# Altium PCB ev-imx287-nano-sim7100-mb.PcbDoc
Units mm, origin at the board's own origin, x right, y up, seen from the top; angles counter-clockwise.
Board outline 100 x 100 mm, 2 copper layers (Top Layer, Bottom Layer); 83 components, 89 nets, 510 pads, 495 vias.
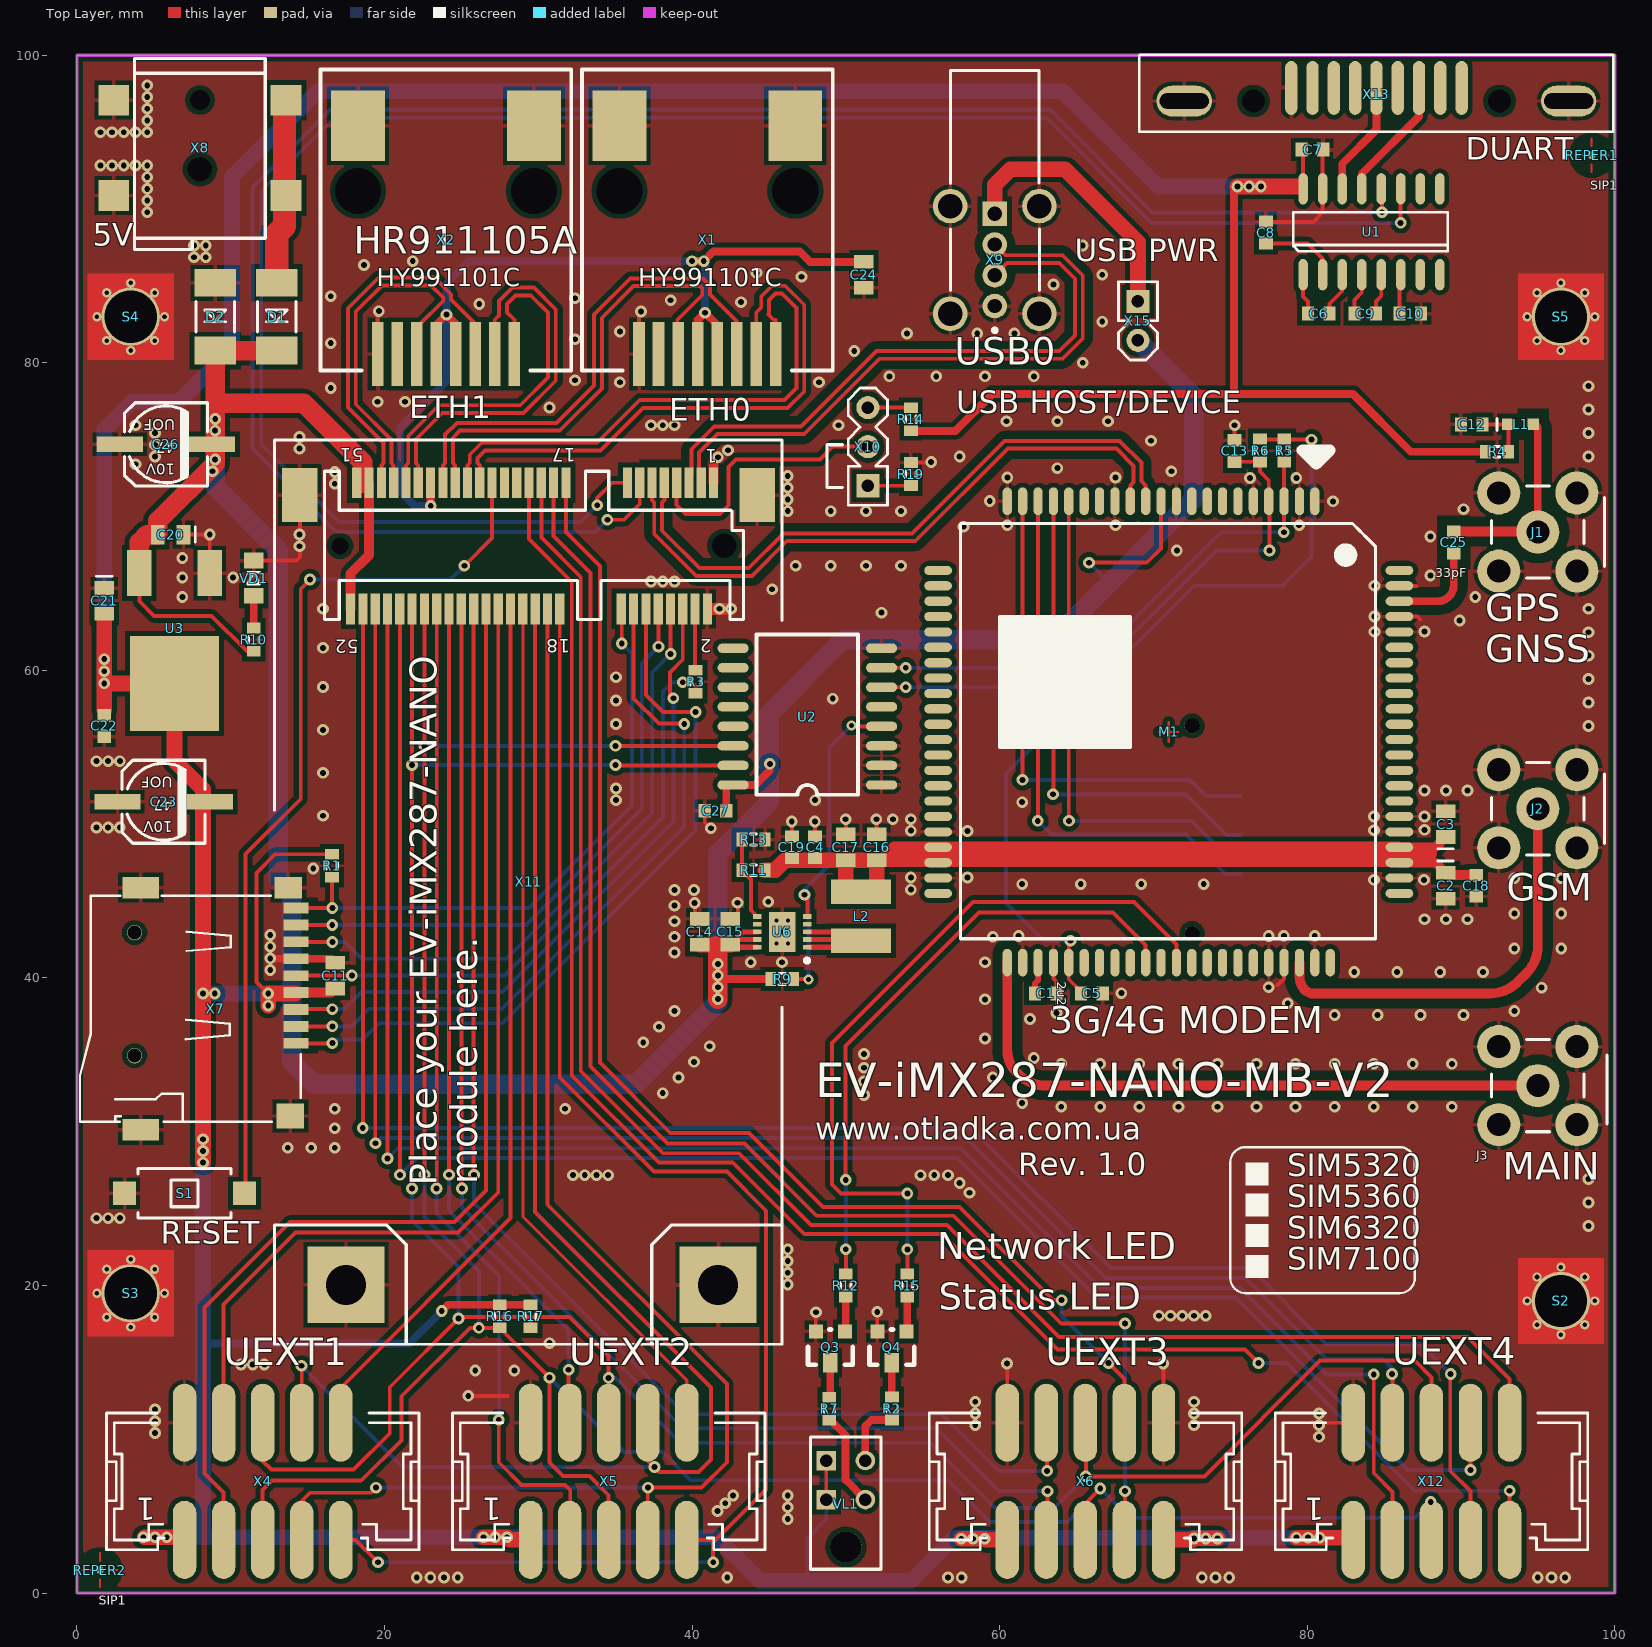
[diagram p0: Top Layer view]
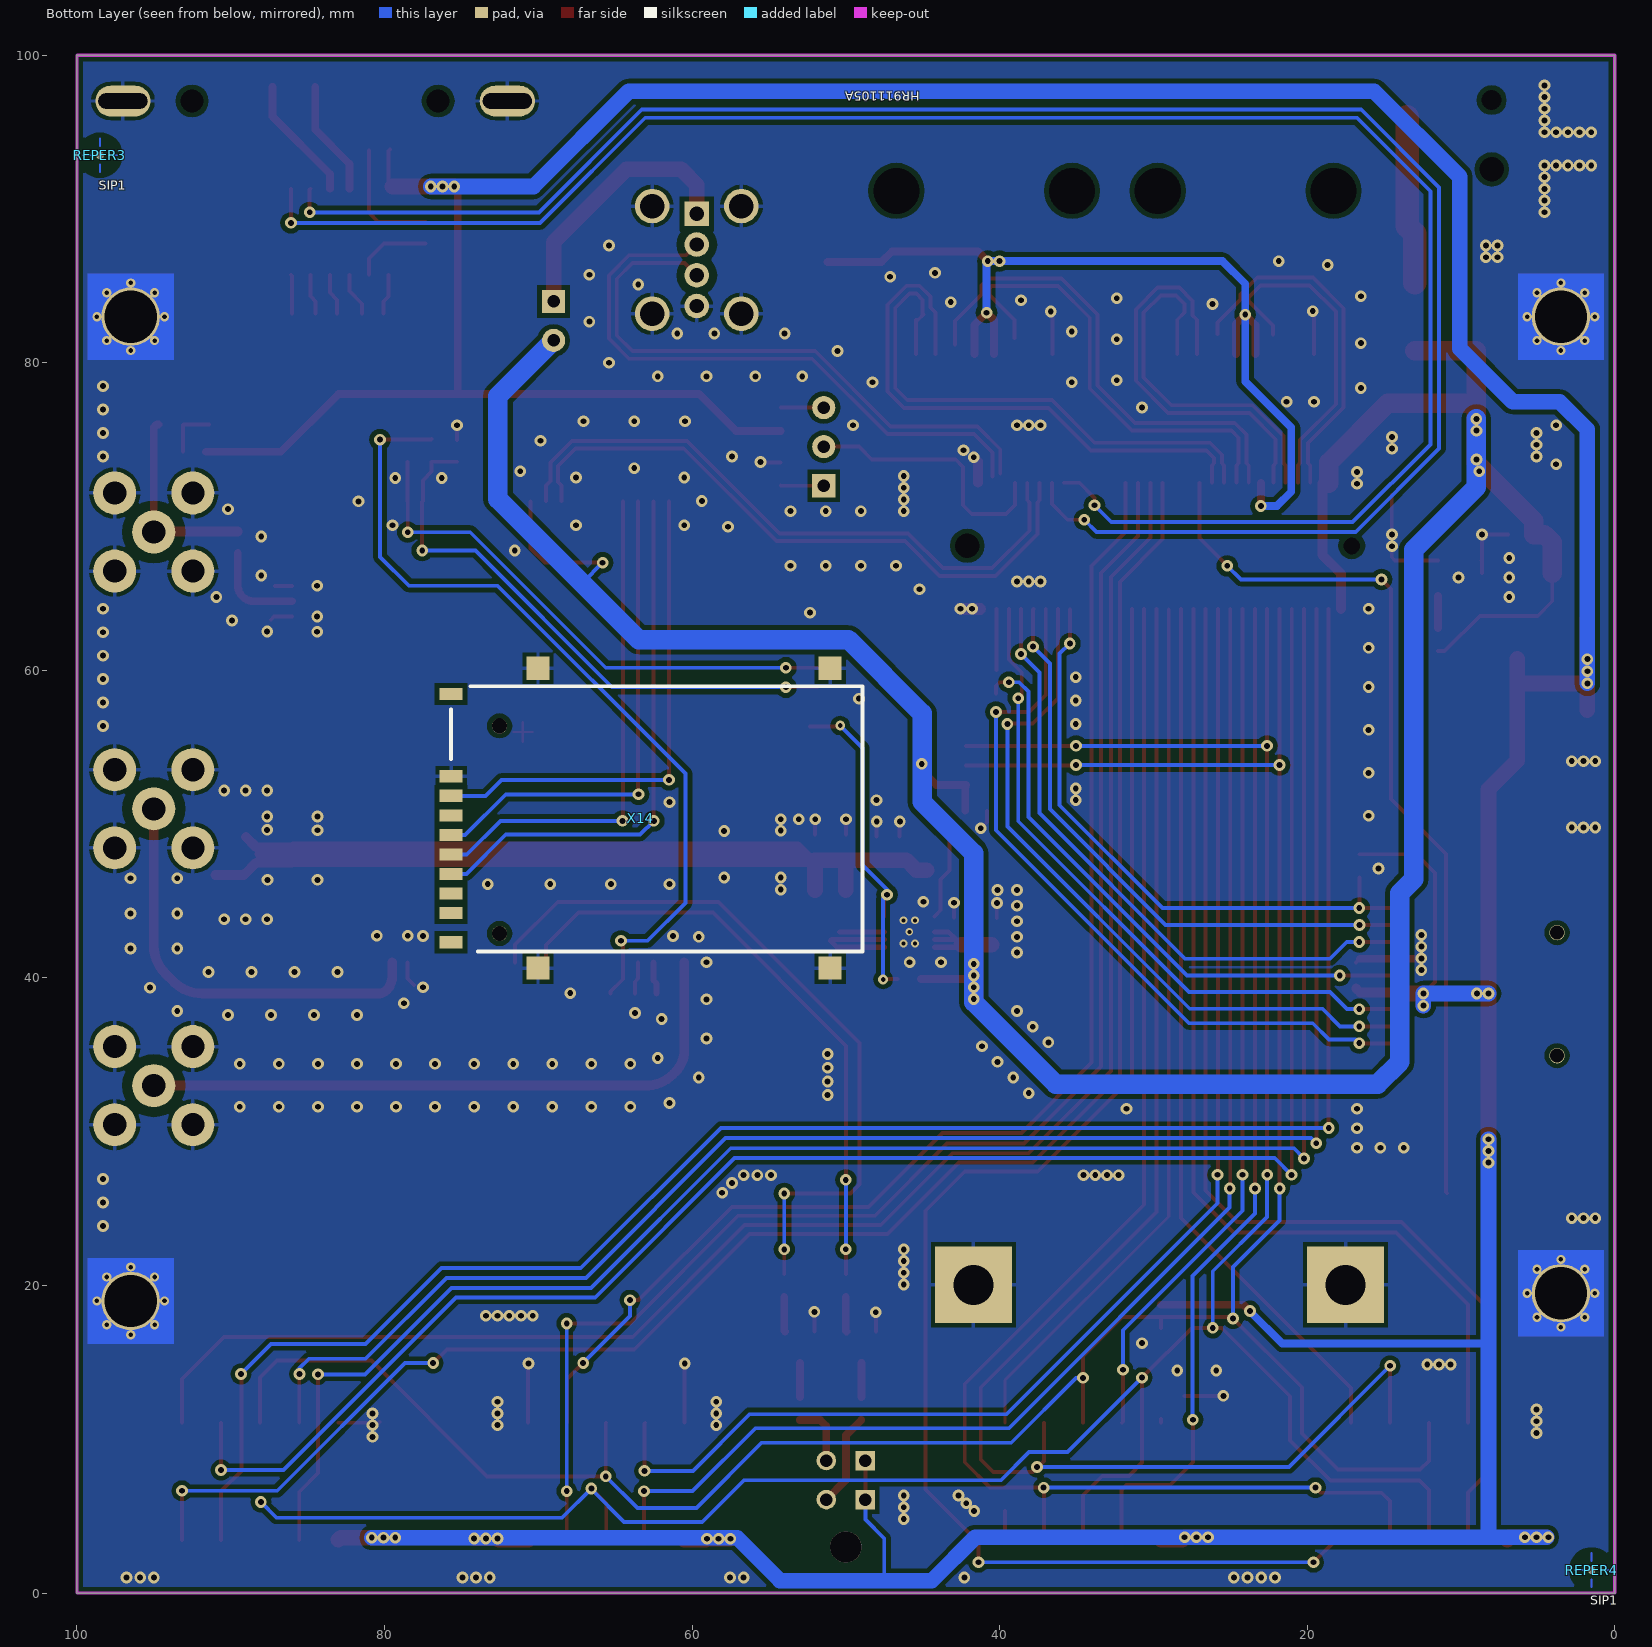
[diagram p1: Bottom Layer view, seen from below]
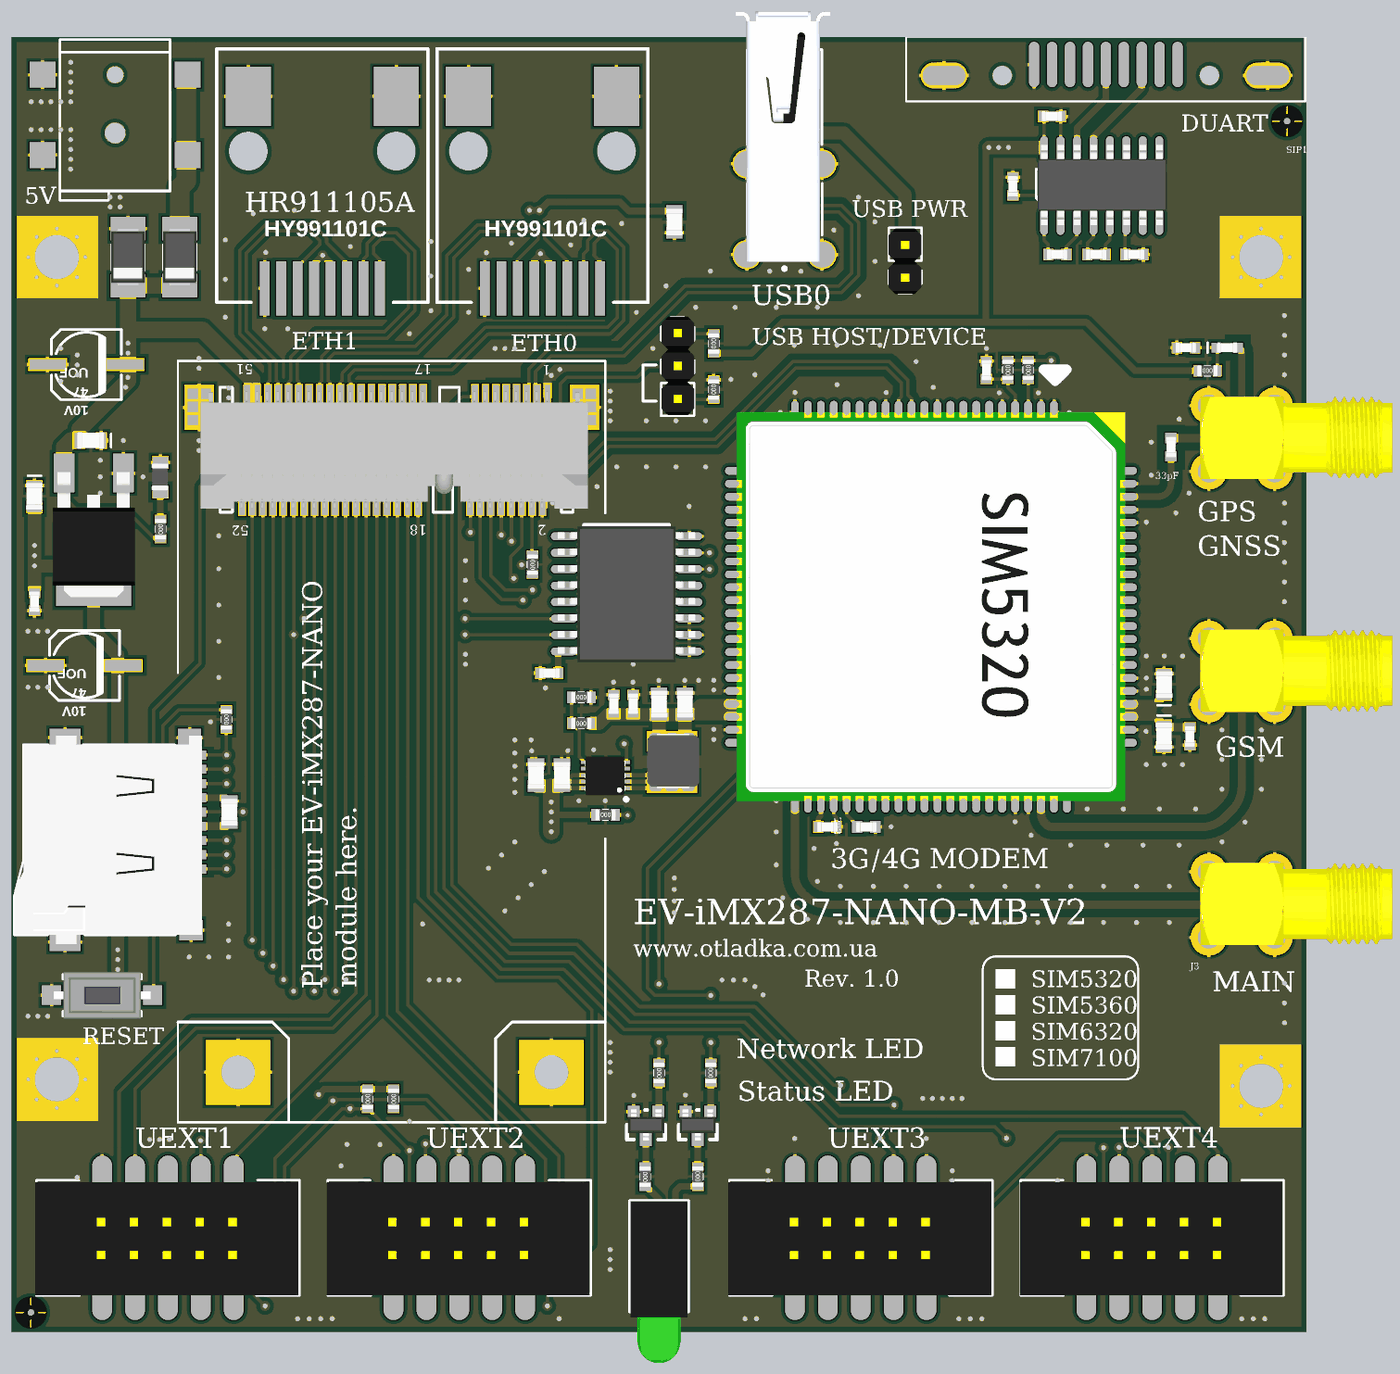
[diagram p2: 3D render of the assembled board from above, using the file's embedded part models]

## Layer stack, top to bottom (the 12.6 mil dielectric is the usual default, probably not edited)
Top Solder: solder mask 0.0102, Solder Resist, Dk 3.5
Top Layer: signal copper 0.0356
Dielectric1: dielectric 0.32, FR-4, Dk 4.8
Bottom Layer: signal copper 0.0356
Bottom Solder: solder mask 0.0102, Solder Resist, Dk 3.5

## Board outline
0,0 100,0 100,100 0,100

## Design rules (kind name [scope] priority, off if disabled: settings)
Clearance Clearance_3 [InNet('USB0_D_P') or InNet('USB0_D_N') or InNet('USB1_D_P') or InNet('USB1_D_N') vs InNet('GND')] p1: gap=0.508
Clearance Clearance_2 [InNet('GSM_ANT') or InNet('GPS_ANT') or InNet('MAIN_ANT') or InNet('NetC25_2') vs InNet('GND')] p2: gap=0.635
Clearance Clearance_1 [InPoly] p3: gap=0.305
Clearance [All] p4: gap=0.152
DiffPairsRouting [All] p1: maxlimit=0.254 minlimit=0.254 mostfreqgap=0.254 toplayer_minwidth=0.254 toplayer_maxwidth=0.254 toplayer_prefwidth=0.254 bottomlayer_minwidth=0.254 bottomlayer_maxwidth=0.254 bottomlayer_prefwidth=0.254 maxuncoupledlength=12.7
PolygonConnect PolygonConnect_2 [(InComponent('S3') or InComponent('S2'))] p1: connectstyle=Relief reliefconductorwidth=0.254 reliefentries=4 polygonreliefangle="45 Angle" airgapwidth=0.254
PolygonConnect PolygonConnect_1 [IsVia] p2: connectstyle=Direct reliefconductorwidth=0.254 reliefentries=4 polygonreliefangle="90 Angle" airgapwidth=0.254
PolygonConnect [IsPad] p3: connectstyle=Relief reliefconductorwidth=0.254 reliefentries=4 polygonreliefangle="90 Angle" airgapwidth=0.254
RoomDefinition ev287-sim7100-mb-rev1.0 [InComponentClass('ev287-sim7100-mb-rev1.0')] p1: confinementstyle=ConfineIn formatcopy=TRUE lockcomponents=FALSE outline -64.135,-65.786 -13.335,-65.786 -13.335,-40.386 -64.135,-40.386
RoutingVias [All] p1: holewidth=0.305 width=0.635 viastyle="Through Hole" minholewidth=0.305 minwidth=0.635 maxholewidth=0.305 maxwidth=0.635
SolderMaskExpansion [All] p1: expansion=0.102
Width [All] p1: maxlimit=2.54 minlimit=0.203 preferedwidth=0.254 minimp=50.000000 maximp=50.000000 favimp=50.000000
29 further rules are at their usual default settings.

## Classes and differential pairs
differential pair USB0_D: +USB0_D_P -USB0_D_N
differential pair USB1_D: +USB1_D_P -USB1_D_N
differential pair ETH0_RX: +ETH0_RX_P -ETH0_RX_N
differential pair ETH0_TX: +ETH0_TX_P -ETH0_TX_N
differential pair ETH1_RX: +ETH1_RX_P -ETH1_RX_N
differential pair ETH1_TX: +ETH1_TX_P -ETH1_TX_N

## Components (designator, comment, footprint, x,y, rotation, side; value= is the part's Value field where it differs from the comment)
C1 "0.1" IPC_C0603#1 63,39 r270 top
C2 "22u" IPC_C0805#1 89,46 r270 top
C3 "22u" IPC_C0805#1 89,50 r90 top
C4 "0.1" IPC_C0603#1 48,48.5 r0 top
C5 "2u2" IPC_C0603#2 66,39 r270 top
C6 "0.1" IPC_C0603#1 80.757,83.2 r90 top
C7 "0.1" IPC_C0603#1 80.351,93.868 r90 top
C8 "0.1" IPC_C0603#1 77.318,88.468 r0 top
C9 "0.1" IPC_C0603#1 83.78,83.2 r90 top
C10 "0.1" IPC_C0603#1 86.701,83.2 r90 top
C11 "22uF" IPC_C0805#2 16.815,40.157 r0 top
C12 "1u" IPC_C0603#1 90.7,76 r90 top
C13 "0.1" IPC_C0603#1 75.286,74.27 r0 top
C14 "22u" ipc_c0805 40.5,43 r0 top
C15 "22u" ipc_c0805 42.5,43 r0 top
C16 "22u" IPC_C0805#2 52,48.5 r0 top
C17 "22u" IPC_C0805#2 50,48.5 r0 top
C18 "0.1" IPC_C0603#1 91,46 r180 top
C19 "0.1" IPC_C0603#1 46.5,48.5 r0 top
C20 "22u" IPC_C0805#1 6.096,68.834 r180 top
C21 "22u" IPC_C0805#1 1.778,64.516 r270 top
C22 "0.1" IPC_C0603#1 1.778,56.388 r0 top
C23 "100u/35V" ALU_SMD_5.3 5.639,51.46 r270 top
C24 "22u" IPC_C0805#2 51.181,85.725 r0 top
C25 "33pF" IPC_C0603#2 89.535,68.326 r0 top
C26 "100u/35V" ALU_SMD_5.3 5.791,74.701 r270 top
C27 "0.1" IPC_C0603#1 41.529,50.876 r270 top
D1 "B340A" SMA 13,83 r90 top
D2 "TVS 6V" SMA 9,83 r90 top
J1 "GPS" SMA_RF 95,69 r90 top
J2 "GSM" SMA_RF 95,51 r90 top
J3 "MAIN" SMA_RF 95,33 r90 top
L1 "FB" L0603 93.875,76 r180 top
L2 "2.2uH/2A" VLCF4020 51,44 r180 top
M1 "SIM7100C" SIM7100C 71,56 r270 top locked
Q3 "BC817" SOT23 49,16 r180 top
Q4 "BC817" SOT23 53,16 r180 top
R1 "10K" IPC_R0603#1 16.586,47.295 r0 top
R2 "510" IPC_R0603#1 53,12 r180 top
R3 "22R" IPC_R0603#1 40.234,59.258 r0 top
R4 "10R" IPC_R0603#1 92.351,74.222 r90 top
R5 "10K" IPC_R0603#1 78.511,74.295 r0 top
R6 "10K" IPC_R0603#1 76.937,74.295 r0 top
R7 "1K" IPC_R0603#2 48.92,11.989 r0 top
R9 "10K" IPC_R0603#2 45.872,39.929 r90 top
R10 "560R" IPC_R0603#1 11.5,62 r0 top
R11 "12K1" IPC_R0603#1 44,47 r270 top
R12 "1K" IPC_R0603#1 50,20 r0 top
R13 "2K" IPC_R0603#2 44,49 r90 top
R14 "1K" IPC_R0603#1 54.229,76.327 r180 top
R15 "1K" IPC_R0603#1 54,20 r180 top
R16 "2K2" IPC_R0603#1 27.5,18 r0 top
R17 "2K2" IPC_R0603#1 29.5,18 r0 top
R19 "1K" IPC_R0603#1 54.229,72.771 r180 top
REPER1 "SIP1" reper2 98.5,93.5 r0 top
REPER2 "SIP1" reper2 1.5,1.5 r0 top
REPER3 "SIP1" reper2 98.5,93.5 r180 bottom
REPER4 "SIP1" reper2 1.5,1.5 r180 bottom
S1 "RESET" TS-101 7,26 r180 top
S2 "SIP1" MOUNTING_HOLE_3MM 96.5,19 r0 top
S3 "SIP1" MOUNTING_HOLE_3MM 3.5,19.5 r0 top
S4 "SIP1" MOUNTING_HOLE_3MM 3.5,83 r0 top
S5 "SIP1" MOUNTING_HOLE_3MM 96.5,83 r0 top
U1 "MAX3232E" SO-16 84.184,88.524 r90 top
U2 "PCF8574" SOL-16 47.498,56.998 r180 top
U3 "NCP1117-33" DPAK 6.35,62.738 r90 top
U6 "NCP1593B" DFN10 47.5,42 r90 top
VD1 "POWER" l0805 11.5,66 r270 top
VL1 "Modem LEDs" LED3_2F 50,3 r0 top
X1 "HR911105A" ETH3A_SMD 41,87.5 r0 top
X2 "HR911105A" ETH3A_SMD 24,87.5 r0 top
X4 "UEXT1" BH10_SMT 7,6 r180 top
X5 "UEXT2" BH10_SMT 29.5,6 r180 top
X6 "UEXT3" BH10_SMT 60.5,6 r180 top (schematic designator X14)
X7 "SDCARD" mSD_TF_push 9,38 r270 top
X8 "POWER" DJK-03-SMD 8.001,93.98 r180 top
X9 "USB0" USB-AC-EDGE 59.69,83.693 r0 top
X10 "USBID" SIP3 51.435,72.009 r90 top
X11 "" PCIEXPRESS_mini 45,76 r180 top
X12 "UEXT4" BH10_SMT 83,6 r180 top
X13 "DUART" DR9P 84.506,100.025 r180 top
X14 "SIM_ASTRON" SIM_ASTRON 75.667,53.111 r90 bottom locked (schematic designator X6)
X15 "USBPWR" SIP2 69,84 r0 top

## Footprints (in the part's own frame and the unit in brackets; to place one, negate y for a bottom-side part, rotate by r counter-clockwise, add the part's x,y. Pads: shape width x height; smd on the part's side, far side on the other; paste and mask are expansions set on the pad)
ALU_SMD_5.3 [mm]
  rect 1x3 smd paste-0.1: 1(0,3) 2(0,-3)
  silkscreen extent -2.7,-2.7 2.7,2.7
BH10_SMT [mil]
  oval 60x200 smd: 1(0,100) 2(0,-200) 3(-100,100) 4(-100,-200) 5(-200,100) 6(-200,-200) 7(-300,100) 8(-300,-200) 9(-400,100) 10(-400,-200)
  silkscreen extent -600,-225 200,125, body extent -597,-219 203,125, height 344
DFN10 [mm]
  rect 0.3x0.56 smd paste-0.025: 1(0,0) 2(0.5,0) 3(1,0) 4(1.5,0) 5(2,0) 6(2,3.258) 7(1.5,3.258) 8(1,3.258) 9(0.5,3.258) 10(0,3.258)
  rect 2.6x1.7 smd paste-1.27: 11(1,1.629)
  rrect50% 0.6x0.6 on Top Paste: 15(0.25,2.054) 15(1,1.629) 16(0.25,1.254) 17(1.65,1.254) 18(1.65,2.054)
  silkscreen extent -1,-0.11 -0.73,0.17, body extent -0.55,0.1 2.45,3.2, height 1
DJK-03-SMD [mm]
  round 1.5 hole 1.6: 0(0,1.4)
  round 1.2 hole 1.3: 0(0,-3.1)
  rect 2x2 smd: 1(5.6,-3.1) 2(-5.6,3.1) 2(-5.6,-3.1) 3(5.6,3.1)
  silkscreen extent -4.25,-5.82 4.25,6.6
DPAK [mm]
  rect 3x1.6 smd: 1(3.59,-2.29) 2(-2,0) 3(3.59,2.29)
  rect 6.2x5.8 smd: 4(-3.59,0)
  body extent -5.98,-3.17 3.66,3.18, height 2.18
DR9P [mm]
  round 1.3 hole 1.5: 0(-8,3) 0(8,3)
  oval 0.8x3.5 smd: 1(-5.54,2.15) 2(-2.77,2.15) 3(0,2.15) 4(2.77,2.15) 5(5.54,2.15) 6(-4.155,2.15) 7(-1.385,2.15) 8(1.385,2.15) 9(4.155,2.15)
  oval 3.6x2 hole 1 slot 3.2 at 0 deg: 10(-12.5,3) 11(12.5,3)
  silkscreen extent -15.4,0 15.43,5
ETH3A_SMD [mm]
  round 2.8 hole 3 unplated: 0(-5.715,3.685) 0(5.715,3.685)
  rect 0.76x4.18 smd: 1(4.445,-6.925) 2(3.175,-6.925) 3(1.905,-6.925) 4(0.635,-6.925) 5(-0.635,-6.925) 6(-1.905,-6.925) 7(-3.175,-6.925) 8(-4.445,-6.925)
  rect 3.5x4.58 smd: 15(-5.715,7.925) 16(5.715,7.925)
  silkscreen extent -8.15,-8 8.15,11.59
IPC_C0603#1 [mm]
  rect 0.9x0.8 smd paste-0.051: 1(0,-0.7) 2(0,0.7)
  body extent -0.39,-0.79 0.41,0.81, height 0.88
IPC_C0603#2 [mm]
  rect 0.9x0.8 smd: 1(0,-0.7) 2(0,0.7)
  body extent -0.39,-0.79 0.41,0.81, height 0.88
IPC_C0805#1 [mil]
  rect 35x50 smd paste-3: 1(-33,0) 2(33,0)
  silkscreen extent -63,-20 -63,20, body extent -42,-26 41,25, height 20
IPC_C0805#2 [mil]
  rect 50x35 smd: 1(0,-33) 2(0,33)
  body extent -25,-42 26,41, height 20
ipc_c0805 [mil]
  rect 50x35 smd: 1(0,-33) 2(0,33)
  body extent -25,-42 26,41, height 20
IPC_R0603#1 [mm]
  rect 0.9x0.7 smd paste-0.051: 1(0,-0.75) 2(0,0.75)
  silkscreen extent -0.35,-0.2 0.35,0.2, body extent -0.44,-0.8 0.46,0.8, height 0.5
IPC_R0603#2 [mm]
  rect 0.9x0.7 smd: 1(0,-0.75) 2(0,0.75)
  silkscreen extent -0.35,-0.2 0.35,0.2, body extent -0.44,-0.8 0.46,0.8, height 0.5
L0603 [mil]
  rect 30x30 smd: 1(32.5,0) 2(-32.5,0)
  silkscreen extent 60,-15 60,15, body extent -31,-16 32,15, height 35
l0805 [mil]
  rect 40x50 smd paste-2: 1(45,0) 2(-45,0)
  silkscreen extent -15,-15 15,15, body extent -42,-27 40,25, height 20
LED3_2F [mil]
  rect 50x50 hole 32: 1(-50,221.26) 3(-50,121.26)
  round 50 hole 32: 2(50,221.26) 4(50,121.26)
  round 80 hole 80: 5(0,0)
  silkscreen extent -90,-57 90,281, body extent -87,-212 87,280, height 378
MOUNTING_HOLE_3MM [mm]
  round 3.8 hole 3.4 mask+0.2: 1(0,0)
  Top Layer region: -2.8,-2.8 2.8,-2.8 2.8,2.8 -2.8,2.8
  Bottom Layer region: -2.8,-2.8 2.8,-2.8 2.8,2.8 -2.8,2.8
mSD_TF_push [mm]
  rect 0.7x1.6 smd: 1(2.25,5.25) 2(1.15,5.25) 3(0.05,5.25) 4(-1.05,5.25) 5(-2.15,5.25) 6(-3.25,5.25) 7(-4.35,5.25) 8(-5.45,5.25) 11(-6.55,5.25)
  rect 1.4x1.8 smd: 12(-7.875,4.75)
  rect 1.4x2.4 smd: 12(-7.875,-4.85) 12(7.875,-4.85)
  rect 1.6x1.8 smd: 12(6.975,4.875)
  round 1 hole 0.9: 13(-4.95,-5.25) 14(3.05,-5.25)
  silkscreen extent -7.35,-8.8 7.35,5.55, body extent -8.05,-8.77 8.05,5.73, height 1.85
PCIEXPRESS_mini [mm]
  rect 2.3x3.5 smd paste-12.7: 0(0.75,4.6) 0(30.5,4.6)
  rect 5x5 hole 2.6: 0(3.3,55.95) 0(27.5,55.95)
  rect 0.6x2 smd paste-0.076: 1(3.6,3.8) 2(4,12) 3(4.4,3.8) 4(4.8,12) 5(5.2,3.8) 6(5.6,12) 7(6,3.8) 8(6.4,12) 9(6.8,3.8) 10(7.2,12) 11(7.6,3.8) 12(8,12) 13(8.4,3.8) 14(8.8,12) 15(9.2,3.8) 16(9.6,12) 17(13.2,3.8) 18(13.6,12) 19(14,3.8) 20(14.4,12) 21(14.8,3.8) 22(15.2,12) 23(15.6,3.8) 24(16,12) 25(16.4,3.8) 26(16.8,12) 27(17.2,3.8) 28(17.6,12) 29(18,3.8) 30(18.4,12) 31(18.8,3.8) 32(19.2,12) 33(19.6,3.8) 34(20,12) 35(20.4,3.8) 36(20.8,12) 37(21.2,3.8) 38(21.6,12) 39(22,3.8) 40(22.4,12) 41(22.8,3.8) 42(23.2,12) 43(23.6,3.8) 44(24,12) 45(24.4,3.8) 46(24.8,12) 47(25.2,3.8) 48(25.6,12) 49(26,3.8) 50(26.4,12) 51(26.8,3.8) 52(27.2,12)
  rect 0.8x0.8 on Top Paste: 14(0.254,5.588) 15(1.27,5.588) 16(0.254,4.572) 17(1.27,4.572) 18(0.254,3.556) 19(1.27,3.556) 20(29.972,5.588) 21(30.988,5.588) 22(29.972,4.572) 23(30.988,4.572) 24(29.972,3.556) 25(30.988,3.556)
  round 1.5 hole 1.6 unplated: R(2.9,7.9)
  round 1 hole 1.1 unplated: R(27.9,7.9)
  silkscreen extent -0.85,1.02 32.15,59.82, body extent 0.49,3.35 30.39,12.43, height 5.15
reper2 [mm]
  round 0.5 smd mask+1: 1(0,0)
  Top Layer lines w0.127: -1.1,0 -0.6,0 ; 0,-1.1 0,-0.6 ; 0,0.6 0,1.1 ; 0.6,0 1.1,0
SIM7100C [mm]
  oval 1.8x0.6 smd: 1(-15,9.5) 2(-15,8.5) 3(-15,7.5) 4(-15,6.5) 5(-15,5.5) 6(-15,4.5) 7(-15,3.5) 8(-15,2.5) 9(-15,1.5) 10(-15,0.5) 11(-15,-0.5) 12(-15,-1.5) 13(-15,-2.5) 14(-15,-3.5) 15(-15,-4.5) 16(-15,-5.5) 17(-15,-6.5) 18(-15,-7.5) 19(-15,-8.5) 20(-15,-9.5) 41(15,-9.5) 42(15,-8.5) 43(15,-7.5) 44(15,-6.5) 45(15,-5.5) 46(15,-4.5) 47(15,-3.5) 48(15,-2.5) 49(15,-1.5) 50(15,-0.5) 51(15,0.5) 52(15,1.5) 53(15,2.5) 54(15,3.5) 55(15,4.5) 56(15,5.5) 57(15,6.5) 58(15,7.5) 59(15,8.5) 60(15,9.5) 81(15,-10.5) 82(-15,-10.5) 85(15,10.5)
  oval 0.6x1.8 smd: 21(-9.5,-15) 22(-8.5,-15) 23(-7.5,-15) 24(-6.5,-15) 25(-5.5,-15) 26(-4.5,-15) 27(-3.5,-15) 28(-2.5,-15) 29(-1.5,-15) 30(-0.5,-15) 31(0.5,-15) 32(1.5,-15) 33(2.5,-15) 34(3.5,-15) 35(4.5,-15) 36(5.5,-15) 37(6.5,-15) 38(7.5,-15) 39(8.5,-15) 40(9.5,-15) 61(9.5,15) 62(8.5,15) 63(7.5,15) 64(6.5,15) 65(5.5,15) 66(4.5,15) 67(3.5,15) 68(2.5,15) 69(1.5,15) 70(0.5,15) 71(-0.5,15) 72(-1.5,15) 73(-2.5,15) 74(-3.5,15) 75(-4.5,15) 76(-5.5,15) 77(-6.5,15) 78(-7.5,15) 79(-8.5,15) 80(-9.5,15) 83(10.5,-15) 84(-10.5,-15) 86(-10.5,15) 87(10.5,15)
  Top Layer lines w0.152: 0,-0.635 0,0.635 ; 0.635,0 -0.635,0
  silkscreen extent -18.32,-13.55 13.45,13.45, body extent -15.01,-15.01 15.01,15.01, height 2.9
SIM_ASTRON [mm]
  round 1 hole 1: 0(-10.22,-3.15) 0(3.28,-3.15)
  rect 0.8x1.5 smd: 1(0,0) 2(-1.27,0) 3(-2.54,0) 4(-3.81,0) 5(-5.08,0) 6(-6.35,0) 7(-7.62,0) 8(-8.89,0) 9(-10.79,0) 10(5.36,0)
  rect 1.5x1.5 smd: 11(7.03,-24.65) 11(7.03,-5.65) 12(-12.47,-24.65) 12(-12.47,-5.65)
  silkscreen extent -11.39,-26.75 5.86,0
SIP2 [mm]
  rect 1.5x1.5 hole 0.813: 1(0,0)
  round 1.5 hole 0.813: 2(0,-2.54)
  silkscreen extent -1.27,-3.81 1.27,1.27, body extent -1.27,-3.86 1.27,1.22, height 7.54
SIP3 [mm]
  rect 1.5x1.5 hole 0.813: 1(0,0)
  round 1.5 hole 0.813: 2(2.54,0) 3(5.08,0)
  silkscreen extent -1.27,-1.27 6.35,1.27, body extent -1.22,-1.3 6.4,1.24, height 7.54
SMA [mm]
  rect 1.8x2.7 smd: 1(2.2,0) 2(-2.2,0)
  silkscreen extent -1,-1.25 1,1.25, body extent -2.19,-1.3 2.19,1.3, height 2.2
SMA_RF [mm]
  round 2.8 hole 1.5: 1(0,0) 2(2.54,-2.54) 3(2.54,2.54) 4(-2.54,2.54) 5(-2.54,-2.54)
  silkscreen extent -3,-4.34 3,3, body extent -3.12,-11.62 3.23,3.19, height 9.67
SO-16 [mil]
  oval 80x24 smd: 1(-110,175) 2(-110,125) 3(-110,75) 5(-110,-25) 6(-110,-75) 7(-110,-125) 8(-110,-175) 9(110,-175) 10(110,-125) 11(110,-75) 12(110,-25) 13(110,25) 14(110,75) 15(110,125) 16(110,175)
  oval 80x24.02 smd: 4(-110,25)
  silkscreen extent -50,-195 50,200, body extent -120,-199 124,195, height 59
SOL-16 [mil]
  oval 80x24 smd: 1(-190,175) 2(-190,125) 3(-190,75) 4(-190,25) 5(-190,-25) 6(-190,-75) 7(-190,-125) 8(-190,-175) 9(190,-175) 10(190,-125) 11(190,-75) 12(190,-25) 13(190,25) 14(190,75) 15(190,125) 16(190,175)
  silkscreen extent -130,-210 130,200, body extent -209,-205 209,208, height 102
SOT23 [mil]
  rect 35.98x50 smd: 1(0.49,40)
  rect 35.98x35.98 smd: 2(-37.5,-40) 3(37.5,-40)
  silkscreen extent -58,-45 58,45, body extent -55,-47 55,49, height 43
TS-101 [mm]
  rect 1.5x1.5 smd: 1(3.9,0) 2(-3.9,0)
  silkscreen extent -3.02,-1.6 3.02,1.6, body extent -3.75,-1.8 3.75,1.8, height 2.5
USB-AC-EDGE [mm]
  rect 1.6x1.6 hole 0.92: 1(0,6)
  round 1.6 hole 0.92: 2(0,4) 3(0,2) 4(0,0)
  round 2.25 hole 1.6: 5(-2.9,-0.5) 6(2.9,-0.5) 7(-2.9,6.5) 8(2.9,6.5)
  silkscreen extent -2.88,-1.7 2.9,15.33, body extent -3.76,-1.04 3.56,18.26, height 14.75
VLCF4020 [mm]
  rect 3.9x1.6 smd paste-2: 1(-0.002,1.578) 2(-0.002,-1.597)
  rrect50% 1x1 on Top Paste: 9(0,1.75) 10(-1.25,1.75) 11(1.25,1.75) 12(-1.25,-1.75) 13(0,-1.75) 14(1.25,-1.75)
  body extent -2.1,-2.2 1.9,2, height 2

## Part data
C1 C4 C5 C6 C7 C8 C9 C10 C11 C12 C13 C18 C19 C20 C21 C22 C24 C25 C27: library part c7
C2 C3 C14 C15 C16 C17 C23 C26: library part CP7
D1 D2: library part "D Schottky", "Schottky Diode"
J1 J2 J3: library part COAX-F, "RF Coaxial PCB Connector, MCX; Thru-Hole, Right-Angle Mount Socket, Blunt Post Terminal, 50 Ohm Impedance"
L1 L2: library part Inductor, "Inductor"
Q3 Q4: library part NPN, "NPN Bipolar Transistor"
R1 R2 R3 R4 R5 R6 R7 R9 R10 R11 R12 R13 R14 R15 R16 R17 R19: library part r7
S1: library part SW-PB, "Switch"
U3: library part TLV1117
VD1: library part LED_GREEN
VL1: library part LED_3_2F
X1 X2: library part HR911105
X4 X5 X6 X12: library part UEXT
X7: library part "uSD card socket"
X8 X10: library part SIP3
X9: library part SIP8
X11: library part SIP2x26
X13: library part SUBD9_M_COUDE
X14: library part SMARTCARD_CONNECTOR
X15: library part SIP2

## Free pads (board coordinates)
  round 1.3 smd: 14(59.69,87.693) 14(59.69,89.693) 15(59.69,85.693) 16(59.69,83.693)
  round 2 smd: 17(56.79,90.193) 18(56.79,83.193) 19(62.59,83.193) 20(62.59,90.193)
  round 1.5 smd: 21(69,81.46) 22(69,84) 23(51.435,77.089) 24(51.435,74.549) 25(51.435,72.009)
  oval 3.3x1.5 smd: 26(97.006,97.025) 27(72.006,97.025)
  round 1.7 smd: 28(92.46,71.54) 29(95,69) 30(97.54,71.54) 31(97.54,66.46) 32(92.46,66.46) 33(92.46,53.54) 34(95,51) 35(97.54,53.54) 36(97.54,48.46) 37(92.46,48.46) 38(92.46,35.54) 39(95,33) 40(97.54,35.54) 41(97.54,30.46) 42(92.46,30.46)
  round 1.2 smd: 43(51.27,8.62) 44(48.73,8.62) 45(48.73,6.08) 46(51.27,6.08)

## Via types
v1: diameter 0.762, hole 0.381, Top Layer to Bottom Layer, tented both sides, 456 vias
v2: diameter 0.6, hole 0.3, Top Layer to Bottom Layer, 32 vias
v3: diameter 0.508, hole 0.254, Top Layer to Bottom Layer, tented both sides, 5 vias
v4: diameter 0.635, hole 0.305, Top Layer to Bottom Layer, tented both sides, 2 vias

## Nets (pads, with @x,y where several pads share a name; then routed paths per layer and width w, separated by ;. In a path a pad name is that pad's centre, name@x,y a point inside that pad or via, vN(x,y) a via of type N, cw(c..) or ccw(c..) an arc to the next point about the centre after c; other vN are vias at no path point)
1V8: C5.1 M1.44 R5.2 R6.2 | length 54.1
  Top Layer w0.254: v1(64.618,42.418) 64.5,42.3 M1.44 64.5,39.919 65.3,39.119 C5.1 ; R6.2 76.975,75.006 v1(80.289,75.006)
  Bottom Layer w0.254: v1(64.618,42.418) 62.89,42.418 60.427,44.882 60.427,53.289 72.644,65.507 78.41,65.507 80.289,67.386 v1(80.289,75.006)
5V: C14.1 C15.1 C20.2 C26.1 C27.2 D1.2 D2.2 M1.11 pad.21 R9.2 R10.1 U2.16 U3.3 U6.8 U6.9 U6.10 X11.49 X11.51 X11.52 X15.2 | length 222.4
  Top Layer w0.254: U3.3 4.06,64.495 5.004,63.551 8.763,63.551 11.064,61.25 R10.1 ; C14.1@40.435,42.227 C14.1 ; C27.2@42.174,50.931 C27.2 ; v1(65.811,67.005) 69.571,67.005 70.5,67.935 M1.11
  Top Layer w0.33: U6.10 42.662,42 C15.1 C15.1@42.838,42.5 ; U6.9 C15.1@42.838,42.5 ; U6.8 43.338,43 C15.1@42.838,42.5
  Top Layer w0.508: v1(41.681,40.157) 41.91,39.929 R9.2 ; C27.2 42.229,52.422 ccw(c42.041,52.422) 42.174,52.555 44.122,52.555 45.06,53.492 v1(45.06,53.924)
  Top Layer w0.635: X11.52 17.8,66.289 19,67.489 X11.49
  Top Layer w1.016: C14.1 C15.1
  Top Layer w1.27: U3.3 4.06,68.322 4.572,68.834 C20.2 5.258,69.723 9,73.465 9,77.377 ; D1.2 D2.2 9,77.377 ; 18.593,72.187 18.593,73.533 14.749,77.377 9,77.377 ; v1(41.681,38.633) v1(41.681,39.395) v1(41.681,40.157) v1(41.681,40.919) 41.681,42.111
  Bottom Layer w0.254: v1(65.811,67.005) 67.094,65.722 67.196,65.722
  Bottom Layer w1.27: v1(9,76.352) 9,71.921 13.081,67.84 13.081,46.406 13.97,45.517 13.97,34.544 15.418,33.096 36.347,33.096 41.681,38.43 v1(41.681,38.633) v1(41.681,39.395) v1(41.681,40.157) v1(41.681,40.919) 41.681,48.108 45.034,51.46 45.034,57.201 49.835,62.001 63.475,62.001 67.196,65.722 72.619,71.145 72.619,77.841 X15.2
  other v1: 8.814,72.949 8.992,73.711 8.992,75.59
CAN_RX0: X11.44 X12.8 | length 118.4
  Top Layer w0.254: v1@21,27.198 X11.44 ; X12.8 90.627,11.073 v1(90.627,8.001)
  Bottom Layer w0.254: v1(21.012,27.198) 22.11,28.296 57.226,28.296 66.294,19.228 75.342,19.228 86.569,8.001 v1(90.627,8.001)
CAN_RX1: X11.48 X12.4 | length 110.7
  Top Layer w0.254: v1@19.4,29.255 X11.48 ; X12.4 v1@85.54,14.249
  Bottom Layer w0.254: v1(19.411,29.255) 19.747,29.591 57.81,29.591 66.904,20.498 75.971,20.498 81.229,15.24 84.912,15.24 85.522,14.63 v1(85.522,14.249)
CAN_TX0: X11.46 X12.3 | length 117.5
  Top Layer w0.254: v1@20.2,28.264 X11.46 ; v1(84.328,14.224) 84.328,7.798 85.54,6.586 X12.3
  Bottom Layer w0.254: v1(20.199,28.264) 20.865,28.931 57.48,28.931 66.573,19.837 75.641,19.837 81.255,14.224 v1(84.328,14.224)
CAN_TX1: X11.50 X12.7 | length 122.4
  Top Layer w0.254: v1@18.6,30.251 X11.50 ; v1@89.306,14.249 89.306,7.95 90.62,6.637 X12.7
  Bottom Layer w0.254: v1(18.593,30.251) 58.115,30.251 67.234,21.133 76.302,21.133 81.229,16.205 87.376,16.205 v1(89.332,14.249)
CPU_RST: S1.2 X11.29 | length 58.2
  Top Layer w0.254: S1.2 10.973,26.073 10.973,48.057 14.554,51.638 14.554,65.303 v1(15.164,65.913) ; v1@25.222,66.827 27,68.605 X11.29
  Bottom Layer w0.254: v1(15.164,65.913) 24.308,65.913 v1(25.197,66.802)
DUART_RXD: U1.12 X11.13 | length 126.4
  Top Layer w0.254: v1(34.493,69.799) 35.585,69.799 36.6,70.814 X11.13 ; U1.12 84.861,91.276 v1(84.861,89.789)
  Bottom Layer w0.254: v1(34.493,69.799) 33.706,69.012 16.84,69.012 11.43,74.422 11.43,91.415 16.485,96.469 63.271,96.469 69.952,89.789 v1(84.861,89.789)
DUART_TXD: U1.11 X11.15@35.8,72.2 | length 124.8
  Top Layer w0.254: v1(33.833,70.739) 33.833,71.222 34.811,72.2 X11.15@35.8,72.2 ; v1(86.081,89.103) 86.081,91.31 U1.11
  Bottom Layer w0.254: v1(33.833,70.739) 32.741,69.647 17.043,69.647 11.989,74.701 11.989,91.161 16.764,95.936 63.043,95.936 69.875,89.103 v1(86.081,89.103)
ETH0_RX_N: X1.6 X11.35 | length 29.9
  Top Layer w0.254: X11.35 24.6,73.33 24.454,73.476 24.454,75.127 24.917,75.59 31.402,75.59 34.138,78.326 34.138,82.931 36.195,84.988 40.513,84.988 40.665,84.836 40.665,84.404 39.04,82.779 X1.6@39.04,81.61
ETH0_RX_P: X1.3 X11.37 | length 32.1
  Top Layer w0.254: X11.37 23.8,73.33 23.946,73.476 23.946,75.337 24.707,76.098 31.191,76.098 33.63,78.537 33.63,83.141 35.985,85.496 40.723,85.496 41.173,85.046 41.173,84.455 42.901,82.728 X1.3@42.901,81.204
ETH0_TX_N: X1.2 X11.31 | length 37.8
  Top Layer w0.254: X11.31 26.2,73.33 26.054,73.476 26.054,73.812 26.537,74.295 34.043,74.295 36.812,77.064 46.212,77.064 47.295,78.146 47.295,83.776 46.057,85.014 45.205,85.014 44.501,84.31 44.501,83.591 44.175,83.266 X1.2
ETH0_TX_P: X1.1 X11.33 | length 36.3
  Top Layer w0.254: X11.33 25.4,73.33 25.546,73.476 25.546,74.023 26.326,74.803 33.833,74.803 36.601,77.572 46.002,77.572 46.787,78.357 46.787,83.566 45.847,84.506 45.415,84.506 45.009,84.099 45.009,83.185 44.958,83.134 45.288,82.804 45.445,82.804 X1.1
ETH1_RX_N: X2.6 X11.45 | length 22
  Top Layer w0.254: X11.45 20.6,73.33 20.454,73.476 20.454,74.988 18.136,77.306 18.136,83.337 19.837,85.039 23.038,85.039 23.825,84.252 23.825,84.023 22.225,82.423 X2.6@22.225,81.839
ETH1_RX_P: X2.3 X11.47 | length 23.6
  Top Layer w0.254: X11.47 19.8,73.33 19.946,73.476 19.946,74.778 17.628,77.096 17.628,83.548 19.627,85.547 23.248,85.547 24.333,84.462 24.333,84.125 25.832,82.626 X2.3@25.832,81.864
ETH1_TX_N: X2.2 X11.41 | length 26.4
  Top Layer w0.254: X11.41 22.2,73.33 22.054,73.476 22.054,75.032 23.756,76.733 29.039,76.733 31.14,78.834 31.14,83.472 29.725,84.887 28.314,84.887 27.457,84.03 27.457,83.086 27.175,82.804 X2.2
ETH1_TX_P: X2.1 X11.43 | length 24.8
  Top Layer w0.254: X11.43 21.4,73.33 21.546,73.476 21.546,75.242 23.545,77.241 28.829,77.241 30.632,79.045 30.632,83.261 29.515,84.379 28.524,84.379 27.965,83.82 27.965,83.284 28.445,82.804 X2.1
ETH_3V3: C24.2 X1.4 X1.5 X2.4 X2.5 X11.39 | length 62.6
  Top Layer w0.508: X11.39 23,70.701 v1(23.012,70.688) ; X2.5 23.365,82.471 v1(24.028,83.134) 24.635,82.528 X2.4 ; v1(40.005,86.614) v1(40.767,86.614) 41.402,87.249 46.99,87.249 47.676,86.563 C24.2 ; X1.5 40.365,82.783 v1(40.843,83.261) 41.635,82.469 X1.4
  Bottom Layer w0.508: v1(23.012,70.688) 21.971,70.688 21.031,71.628 21.031,75.794 24.028,78.791 v1(24.028,83.134) 24.028,85.141 25.502,86.614 v1(40.005,86.614) v1(40.767,86.614) 40.843,86.538 v1(40.843,83.261)
GND: C1.2 C2.2 C3.2 C4.2 C5.2 C7.1 C8.2 C10.1 C11.2 C12.2 C13.2 C14.2 C15.2 C16.2 C17.2 C18.2 C19.2 C20.1 C21.1 C22.1 C23.2 C24.1 C26.2 C27.1 D2.1 J1.2 J1.3 J1.4 J1.5 J2.2 J2.3 J2.4 J2.5 J3.2 J3.3 J3.4 J3.5 M1.1 M1.2 M1.5 M1.10 M1.14 M1.37 M1.40 M1.41 M1.43 M1.57 M1.58 M1.60 M1.61 M1.64 M1.65 M1.77 M1.78 M1.80 M1.82 pad.16 pad.17 pad.18 pad.19 pad.20 pad.26 pad.27 pad.28 pad.30 pad.31 pad.32 pad.33 pad.35 pad.36 pad.37 pad.38 pad.40 pad.41 pad.42 Q3.3 Q4.3 R13.1 R19.1 S1.1 S2.1 S3.1 S4.1 S5.1 U1.15 U2.1 U2.2 U2.3 U2.8 U3.1 U6.11 VD1.2 X1.8 X1.15 X1.16 X2.8 X2.15 X2.16 X4.2 X5.2 X6.2 X6.10 X7.6 X7.12 X8.1 X8.3 X9.4 X9.5 X9.6 X9.7 X9.8 X11.0 X11.1 X11.2 X12.2 X13.5 X13.10 X13.11 X14.1 X14.11 X14.12 | length 64.3
  Top Layer w0.254: v1@5.105,11.074 v1@5.111,11.08 ; C20.1 8.23,68.834 8.64,68.424 U3.1@8.64,67.132 ; U3.1 U3.1@8.64,67.132 ; U3.1@8.651,67.143 U3.1@8.64,67.132 ; VD1.2 14.286,67.143 14.5,67.357 X11.0@14.5,71.4 ; v1(12.573,41.275) v1@12.7,41.275 ; C11.2@16.56,41.25 C11.2 ; X2.8 19.555,83.284 v1(19.634,83.363) ; v1(25.451,12.827) 27.991,12.827 ; X5.2 X5.2@29.5,11.318 ; X1.8 36.555,83.215 v1(36.678,83.337) ; C14.2@40.183,43.891 v1@40.183,44.858 ; C27.1 40.829,50.128 v1(41.224,49.733) ; 41.4,73.582 41.4,73.887 v1@41.681,74.168 ; C15.2@42.977,43.917 v1@42.977,44.883 ; C19.2 v1@46.5,50.166 ; C4.2 v1@48,50.166 ; Q3.3 48.048,18.253 v1(48.057,18.263) ; v1(49.987,50.317) 50,50.305 C17.2 ; C16.2 v1@52,50.305 ; v1(52.045,18.288) 52.048,18.285 Q4.3 ; R19.1 55.512,73.521 v1(55.55,73.558) ; v1(60.477,14.935) 60.5,14.913 X6.2 ; M1.43 63.5,39.954 63.7,39.754 C1.2 ; v1(70.637,14.935) 70.66,14.913 X6.10 ; C13.2 v1(75.286,75.946) ; C8.2 80.405,89.168 81.009,89.772 U1.15 C7.1@81.009,93.826 ; 78.08,39.548 78.5,39.968 M1.58 ; 80.315,11.125 80.36,11.08 X12.2 ; M1.78 87.173,63.5 87.376,63.297 ; M1.80 87.115,65.5
  Top Layer w0.508: v1@12.7,41.275 12.725,41.25 X7.6 C11.2@16.56,41.25
  Top Layer w0.635: X11.1 41.4,73.582 v1(41.681,73.863)
  Top Layer w0.762: X11.2@41.254,64 v1@42.545,64
  other v1: 22.098,1.016 22.987,1.016 23.876,1.016 24.765,1.016 42.291,1.016 56.642,1.016 57.531,1.016 73.152,1.016 74.041,1.016 74.93,1.016 94.996,1.016 95.885,1.016 96.774,1.016 46.228,4.826 41.656,5.334 46.228,5.588 42.164,5.842 42.672,6.35 46.228,6.35 80.772,10.16 5.08,10.414 58.42,10.922 72.644,10.922 80.772,10.922 5.08,11.176 58.42,11.684 72.644,11.684 80.772,11.684 5.08,11.938 58.42,12.446 72.644,12.446 25.908,14.478 28.448,14.478 10.668,14.859 11.43,14.859 12.192,14.859 30.734,16.256 70.358,18.034 71.12,18.034 71.882,18.034 72.644,18.034 73.406,18.034 46.228,20.066 46.228,20.828 46.228,21.59 46.228,22.352 98.298,23.876 1.27,24.384 2.032,24.384 2.794,24.384 98.298,25.4 58.039,26.035 57.404,26.67 98.298,26.924 32.258,27.178 33.02,27.178 33.782,27.178 34.544,27.178 54.864,27.178 55.753,27.178 56.642,27.178 13.716,28.956 15.24,28.956 16.764,28.956 16.764,30.226 16.764,31.496 31.75,31.496 64.008,31.623 66.548,31.623 69.088,31.623 71.628,31.623 74.168,31.623 76.708,31.623 79.248,31.623 81.788,31.623 84.328,31.623 86.868,31.623 89.408,31.623 61.468,31.877 51.181,32.385 38.1,32.512 51.181,33.274 39.116,33.528 59.563,33.528 51.181,34.163 64.008,34.417 66.548,34.417 69.088,34.417 71.628,34.417 74.168,34.417 76.708,34.417 79.248,34.417 81.788,34.417 84.328,34.417 86.868,34.417 89.408,34.417 40.132,34.544 62.23,34.798 51.181,35.052 41.148,35.56 36.83,35.814 59.055,36.068 37.846,36.83 61.976,37.338 81.788,37.592 84.582,37.592 87.376,37.592 90.17,37.592 63.703,37.719 38.862,37.846 93.472,37.846 78.74,38.354 59.055,38.608 67.92,39.014 95.25,39.37 77.495,39.395 83.058,40.386 85.852,40.386 88.646,40.386 91.44,40.386 12.573,40.513 43.815,41.021 45.847,41.021 59.055,41.021 38.862,41.656 93.472,41.91 96.52,41.91 12.573,42.037 38.862,42.672 59.563,42.672 61.239,42.723 77.495,42.723 78.486,42.748 80.493,42.748 12.573,42.799 38.862,43.688 87.63,43.815 89.027,43.815 90.424,43.815 93.472,44.196 96.52,44.196 38.862,44.704 40.17,44.87 42.964,44.896 44.958,44.958 38.862,45.72 40.132,45.72 54.229,45.745 61.468,46.101 65.278,46.101 69.215,46.101 73.279,46.101 84.353,46.38 87.605,46.38 93.472,46.482 96.52,46.482 54.229,46.533 57.912,46.533 15.367,47.117 57.912,49.555 54.229,49.581 84.353,49.606 87.63,49.632 1.27,49.784 2.032,49.784 2.794,49.784 46.487,50.179 47.987,50.179 51.987,50.317 53.061,50.317 54.229,50.317 84.353,50.495 87.63,50.495 16.002,50.546 61.468,51.435 35.052,51.562 48.006,51.562 87.63,52.197 89.027,52.197 90.424,52.197 35.052,52.324 16.002,53.34 1.27,54.102 2.032,54.102 2.794,54.102 16.002,56.134 98.298,56.388 35.052,56.515 98.298,57.912 35.052,58.039 49.149,58.166 16.002,58.928 98.298,59.436 35.052,59.563 98.298,60.96 16.002,61.468 98.298,62.484 84.379,62.509 87.63,62.535 89.916,63.246 84.379,63.5 52.324,63.754 16.002,64.008 41.783,64.008 42.545,64.008 98.298,64.008 6.858,64.77 90.932,64.77 45.212,65.278 84.379,65.507 37.338,65.786 38.1,65.786 38.862,65.786 6.858,66.04 10.16,66.04 88.011,66.167 46.736,66.802 49.022,66.802 51.308,66.802 53.594,66.802 6.858,67.31 71.526,67.793 14.478,68.072 88.011,68.707 8.636,68.834 14.478,68.834 57.658,69.342 60.503,69.444 67.539,69.444 79.477,69.444 46.228,70.358 49.022,70.358 51.308,70.358 53.594,70.358 90.17,70.485 81.686,70.993 59.36,71.018 46.228,71.12 46.228,71.882 16.764,72.136 76.276,72.517 79.299,72.517 60.503,72.542 67.539,72.542 46.228,72.644 16.764,72.898 71.171,72.949 63.754,73.152 3.81,73.406 5.08,73.914 57.404,73.914 98.298,73.914 42.342,74.32 14.478,74.422 5.08,74.676 69.85,74.93 14.478,75.184 5.08,75.438 98.298,75.438 3.81,75.946 37.338,75.946 38.1,75.946 38.862,75.946 49.53,75.946 60.452,76.2 63.754,76.2 67.056,76.2 98.298,76.962 30.734,77.089 19.558,77.47 21.336,77.47 16.51,78.359 98.298,78.486 35.306,78.74 48.26,78.74 32.385,78.867 52.832,79.121 55.88,79.121 59.055,79.121 62.23,79.121 65.405,80.01 50.546,80.772 16.51,81.28 32.385,81.534 53.975,81.915 58.547,81.915 60.96,81.915 35.306,82.042 66.675,82.677 26.162,83.82 43.18,83.947 38.608,84.074 32.385,84.201 16.51,84.328 63.5,85.09 47.117,85.598 66.675,85.725 44.196,85.852 18.669,86.36 21.844,86.614 7.62,86.868 8.382,86.868 7.62,87.63 8.382,87.63 65.405,87.63 4.572,89.789 4.572,90.551 4.572,91.313 4.572,92.075 1.524,92.837 2.286,92.837 3.048,92.837 3.81,92.837 4.572,92.837 1.524,94.996 2.286,94.996 3.048,94.996 3.81,94.996 4.572,94.996 4.572,95.758 4.572,96.52 4.572,97.282 4.572,98.044
  other v2: 96.5,16.8 3.5,17.3 94.944,17.444 98.056,17.444 1.944,17.944 5.056,17.944 94.3,19 98.7,19 1.3,19.5 5.7,19.5 94.944,20.556 98.056,20.556 1.944,21.056 5.056,21.056 96.5,21.2 3.5,21.7 3.5,80.8 96.5,80.8 1.944,81.444 5.056,81.444 94.944,81.444 98.056,81.444 1.3,83 5.7,83 94.3,83 98.7,83 1.944,84.556 5.056,84.556 94.944,84.556 98.056,84.556 3.5,85.2 96.5,85.2
  other v3: 45.496,42.25 46.246,42.25 45.871,43 45.496,43.75 46.246,43.75
GPS_ANT: C25.1 M1.79 | length 6.2
  Top Layer w0.508: M1.79 88.503,64.5 ccw(c88.503,65.532) 89.535,65.532 C25.1
GSM_ANT: J2.1 M1.59 pad.34 | length 27.7
  Top Layer w0.635: M1.59 79.5,40.081 ccw(c80.721,40.081) 79.858,39.218 ccw(c80.409,39.769) 80.409,38.989 91.886,38.989 ccw(c91.886,41.529) 93.683,39.733 94.256,40.306 ccw(c92.46,42.103) 95,42.103 pad.34
I2C0_SCL: R16.1 U2.14 X4.5 X5.5 X6.5 X11.40 X12.5 | length 177.3
  Top Layer w0.254: X4.5 12.08,6.695 12.7,7.315 18.491,7.315 21.107,9.931 21.107,12.802 25.552,17.247 v1(26.137,17.247) 27.497,17.247 v1(30.734,14.009) 30.734,8.484 31.598,7.62 33.325,7.62 34.58,6.365 X5.5 ; v1@22.6,27.203 X11.40 ; v1@35.027,55.095 U2.14@42.174,55.095 ; X6.5 65.58,5.839 v1(66.548,6.807)
  Bottom Layer w0.254: v1@22.606,27.203 22.606,24.46 26.137,20.93 v1(26.137,17.247) ; v1(22.606,55.093) v1(35.027,55.093) ; v1(30.734,14.009) 35.574,9.169 38.075,9.169 39.903,7.341 56.617,7.341 59.334,4.623 64.414,4.623 66.548,6.756 v1(66.548,6.807) 68.453,4.902 87.02,4.902 v1(88.036,5.918)
  other v1: 22.599,27.203
I2C0_SDA: R17.1 U2.15 X4.6 X5.6 X6.6 X11.42 X12.6 | length 173
  Top Layer w0.254: X4.6 12.08,8.596 12.649,8.026 17.983,8.026 20.345,10.389 20.345,13.386 24.917,17.958 29.489,17.958 ; v1@21.8,26.314 X11.42 ; R17.1 29.5,17.947 29.489,17.958 ; X5.6 v1(34.58,13.995) 34.58,15.407 32.029,17.958 29.489,17.958 ; v1@34.849,53.848 34.872,53.825 U2.15@42.174,53.825 ; X6.6 65.608,11.052 v1(65.608,7.595) 73.33,7.595 80.848,15.113 86.995,15.113 88.08,14.028 X12.6
  Bottom Layer w0.254: v1@21.793,26.314 21.793,24.232 24.816,21.209 v1(24.816,17.856) ; v1(21.793,53.848) v1(35.027,53.848) ; v1(34.58,13.995) 35.027,13.995 39.243,9.779 55.474,9.779 59.715,5.537 63.551,5.537 v1(65.608,7.595)
  other v1: 21.786,26.314
LDO_3V3: C7.2 C11.1 C21.2 C22.2 C23.1 pad.44 pad.45 R1.2 R4.2 R14.2 R16.2 R17.2 U1.16 U3.2 U3.4 VL1.1 VL1.3 X4.1 X5.1 X6.1 X6.9 X7.4 X12.1 | length 389.5
  Top Layer w0.254: v1(12.446,38.989) 11.684,39.751 11.684,46.838 12.891,48.045 R1.2 ; pad.45 pad.44 ; C7.2 79.739,93.78 U1.16
  Top Layer w0.508: v1(23.724,18.339) 24.135,18.75 R16.2 R17.2 ; R14.2 57.137,75.577 59.538,77.978 75.235,77.978 ; v1(75.463,91.465) 75.235,91.237 75.235,77.978 ; R4.2 86.738,74.222 82.982,77.978 75.235,77.978
  Top Layer w0.635: X7.4 16.546,39.05 C11.1
  Top Layer w1.016: C22.2@1.778,57.404 v1(1.778,59.157) ; C21.2@1.778,63.373 v1(1.778,59.157) ; v1@4.42,3.632 6.828,3.632 cw(c6.828,3.46) X4.1 ; U3.4 1.787,59.148 v1(1.778,59.157) ; U3.2 6.35,54.124 8.204,52.27 v1(8.204,38.989) ; v1(8.204,27.991) v1(8.204,28.753) v1(8.204,29.515) v1@8.204,38.964 ; v1(12.446,38.202) v1(12.446,38.989) X7.4@14.189,38.989 ; v1(26.441,3.632) v1(27.965,3.632) 28.138,3.46 X5.1 ; v1(57.506,3.531) v1(59.03,3.531) 59.1,3.46 X6.1 ; X6.9 72.548,3.46 v1(72.644,3.556) v1(74.168,3.556) ; v1(75.463,91.465) v1(76.225,91.465) v1(76.987,91.465) U1.16@79.477,91.465 ; v1(79.299,3.607) 82.853,3.607 X12.1
  Bottom Layer w0.254: 8.204,16.535 8.509,16.231 ; 47.498,0.813 47.498,3.556 48.73,4.788 VL1.3
  Bottom Layer w0.508: 8.509,16.231 21.615,16.231 v1(23.724,18.339)
  Bottom Layer w1.016: v1(1.778,59.157) 1.778,75.667 3.581,77.47 6.629,77.47 10.084,80.924 10.084,92.1 15.646,97.663 64.11,97.663 70.307,91.465 v1(75.463,91.465) v1(76.225,91.465) v1(76.987,91.465) ; v1@4.42,3.632 8.28,3.632 ; v1(8.204,29.515) 8.204,16.535 8.204,3.708 8.28,3.632 ; v1(8.204,38.989) v1(8.966,38.989) v1(12.446,38.989) v1(12.446,38.202) ; v1(80.823,3.607) 57.074,3.607 54.28,0.813 47.498,0.813 44.399,0.813 41.58,3.632 v1(27.965,3.632) 8.28,3.632
  other v1: 58.268,3.531 73.406,3.556 80.061,3.607 4.318,3.632 5.08,3.632 5.842,3.632 27.203,3.632 1.778,59.944 1.778,60.731
MAIN_ANT: J3.1 M1.81 pad.39 | length 41.4
  Top Layer w0.635: M1.81 60.5,35.301 ccw(c62.504,35.301) 61.087,33.884 61.227,33.744 ccw(c63.023,35.54) 63.023,33 pad.39
MODEM_POWER: R9.1 U2.4 U6.5 | length 22.5
  Top Layer w0.254: R9.1 47.549,39.929 v4(47.574,39.903) ; v1(47.32,45.415) 47.5,45.235 U6.5 ; v4(50.368,56.413) 50.419,56.363 U2.4
  Bottom Layer w0.254: v1@47.219,45.517 v1(47.32,45.415) ; v4(47.574,39.903) 47.574,45.161 v1(47.32,45.415) ; v4(50.368,56.413) 48.92,54.966 48.92,47.346 47.32,45.745 v1(47.32,45.415)
NetC6_1: C6.1 U1.3 | length 2.9
  Top Layer w0.254: C6.1 81.457,83.845 82.279,84.667 U1.3
NetC6_2: C6.2 U1.1 | length 2.7
  Top Layer w0.254: U1.1 79.739,84.32 80.057,84.001 C6.2
NetC8_1: C8.1 U1.2 | length 5.2
  Top Layer w0.254: C8.1 80.024,87.768 81.009,86.783 U1.2
NetC9_1: C9.1 U1.5 | length 2.7
  Top Layer w0.254: C9.1 84.48,83.997 84.819,84.336 U1.5
NetC9_2: C9.2 U1.4 | length 2.7
  Top Layer w0.254: C9.2 83.08,84.096 83.549,84.565 U1.4
NetC10_2: C10.2 U1.6 | length 2.6
  Top Layer w0.254: C10.2 86.001,85.642 U1.6
NetC12_1: C12.1 L1.1 R4.1 | length 3.4
  Top Layer w0.254: C12.1 L1.1 93.101,75.948 R4.1
NetC25_2: C25.2 J1.1 L1.2 pad.29 | length 11.9
  Top Layer w0.508: L1.2 cw(c94.7,75.7) 95,75.7 pad.29
  Top Layer w0.635: C25.2 pad.29@94.25,69.026
NetD1_1: D1.1 X8.2 | length 11
  Top Layer w1.524: D1.1 13,88.387 13.5,88.887 13.5,90.9 13.5,96.012
NetL2_1: L2.1 U6.1 U6.2 U6.3 | length 10.1
  Top Layer w0.33: U6.1 50.58,42 L2.1 50.923,42.5 U6.2 ; U6.3 L2.1@50.423,43
NETLIGHT: M1.51 R15.1 | length 48.1
  Top Layer w0.254: R15.1 v1(54,22.352) ; v1(54,25.984) 49.682,25.984 49.098,26.568 49.098,35.763 58.268,44.933 68.732,44.933 71.5,42.165 M1.51
  Bottom Layer w0.254: v1(54,22.352) v1(54,25.984)
NetM1_17: M1.17 X14.5 | length 32.8
  Top Layer w0.254: v1@64.5,50.216 M1.17
  Bottom Layer w0.254: v1(64.516,50.216) 72.466,50.216 74.651,48.031 X14.5
NetM1_18: M1.18 X14.4 | length 32.3
  Top Layer w0.254: v1@63.5,51.943 M1.18
  Bottom Layer w0.254: v1(63.475,51.943) 72.111,51.943 74.752,49.301 X14.4
NetM1_19: M1.19 X14.6 | length 35.4
  Top Layer w0.254: M1.19 62.5,50.225 v1@62.509,50.216
  Bottom Layer w0.254: v1(62.484,50.216) 63.373,49.327 72.111,49.327 74.676,46.761 X14.6
NetM1_20: M1.20 X14.2 | length 32.7
  Top Layer w0.254: v1@61.5,52.883 M1.20
  Bottom Layer w0.254: v1(61.493,52.883) 72.39,52.883 73.431,51.841 X14.2
NetQ3_1: Q3.1 R7.2 | length 2.2
  Top Layer w0.508: Q3.1 48.988,12.762 R7.2@49,12.75
NetQ3_2: Q3.2 R12.1 | length 2.3
  Top Layer w0.508: Q3.2 50,17.063 R12.1
NetQ4_1: Q4.1 R2.1 | length 2.2
  Top Layer w0.508: Q4.1 52.988,12.762 R2.1
NetQ4_2: Q4.2 R15.2 | length 2.3
  Top Layer w0.508: Q4.2 54,17.064 R15.2
NetR2_2: pad.43 R2.2 VL1.2 | length 4.1
  Top Layer w0.508: pad.43 51.27,10.859 51.661,11.25 R2.2
NetR7_1: pad.46 R7.1 VL1.4 | length 6.1
  Top Layer w0.508: R7.1@49,11.25 49.987,10.263 49.987,7.363 pad.46
NetR10_2: R10.2 VD1.1 | length 2.1
  Top Layer w0.508: R10.2 VD1.1
NetR11_1: R11.1 R13.2 U6.6 | length 5.4
  Top Layer w0.254: R13.2 R11.1 43.84,46.41 43.84,44.402 U6.6
NetR14_1: pad.23 R14.1 X10.3 | length 2.8
  Top Layer w0.254: pad.23 54.217,77.089 R14.1
NetR19_2: pad.25 R19.2 X10.1 | length 2.8
  Top Layer w0.254: pad.25 54.217,72.009 R19.2
NetU1_13: U1.13 X13.2 | length 8.2
  Top Layer w0.508: U1.13 83.549,92.287 87.276,96.013 X13.2@87.276,97.951
NetU1_14: U1.14 X13.3 | length 7.6
  Top Layer w0.508: U1.14 82.279,92.947 84.506,95.174 X13.3@84.506,97.951
POWERKEY: M1.3 R5.1 U2.7 | length 34.9
  Top Layer w0.254: U2.7@51.826,60.175 53.896,60.175 v1(53.899,60.173) ; v1(78.486,68.986) M1.3@78.486,70.986 ; M1.3 78.5,73.534 R5.1
  Bottom Layer w0.254: v1(53.899,60.173) 65.608,60.173 74.422,68.986 v1(78.486,68.986)
POWERON_5320: X11.25@28.6,72.2
RESET_5320: X11.27
RESET_GSM: C13.1 M1.4 R6.1 U2.6 | length 37.1
  Top Layer w0.254: U2.6@51.826,58.905 53.896,58.905 v1(53.899,58.903) ; C13.1 76.912,73.57 R6.1 76.937,72.923 77.5,72.36 M1.4 77.546,70.954 v1(77.546,67.793)
  Bottom Layer w0.254: v1(53.899,58.903) 65.202,58.903 74.092,67.793 v1(77.546,67.793)
SSP0_CLK: R3.2 X11.4 | length 4
  Top Layer w0.254: R3.2@40.2,60.008 X11.4
SSP0_CLKR: R3.1 X7.5 | length 39.3
  Top Layer w0.254: X7.5 v1@17.882,40.15 ; v1(39.395,59.233) 40.005,59.233 40.234,59.004 R3.1
  Bottom Layer w0.254: v1(17.882,40.157) 27.813,40.157 38.125,50.47 38.125,58.623 38.735,59.233 v1(39.395,59.233)
SSP0_CMD: X7.3 X11.6 | length 43.8
  Top Layer w0.254: X7.3 14.279,37.979 16.605,37.979 v1(16.612,37.973) ; v1@38.557,58.191 38.557,59.868 39.4,60.711 X11.6
  Bottom Layer w0.254: v1(16.612,37.973) 17.399,37.973 18.517,39.091 27.686,39.091 38.786,50.19 v1(38.786,58.191)
SSP0_DAT0: X7.7 X11.8 | length 41.3
  Top Layer w0.254: X7.7 v1@16.612,42.35 ; X11.8 38.608,63.992 v1(38.608,61.062)
  Bottom Layer w0.254: v1(16.612,42.342) 17.424,42.342 18.517,41.25 27.94,41.25 37.414,50.724 37.414,59.868 v1(38.608,61.062)
SSP0_DAT1: X7.8 X11.10 | length 39.1
  Top Layer w0.254: X7.8 v1(16.602,43.45) ; X11.10 37.821,63.979 v1(37.821,61.544)
  Bottom Layer w0.254: v1(16.602,43.45) 29.201,43.45 36.728,50.978 36.728,60.452 v1(37.821,61.544)
SSP0_DAT2: X7.1 X11.12 | length 48.7
  Top Layer w0.254: X7.1 v1@16.612,35.75 ; X11.12 37,58.402 38.1,57.302 v1(40.234,57.302)
  Bottom Layer w0.254: v1(16.612,35.763) 16.84,35.992 18.567,35.992 19.634,37.059 27.686,37.059 40.234,49.606 v1(40.234,57.302)
SSP0_DAT3: X7.2 X11.14@36.2,64 | length 47.1
  Top Layer w0.254: X7.2 v1@16.612,36.85 ; X11.14@36.2,64 36.2,58.186 37.846,56.54 v1@39.268,56.54
  Bottom Layer w0.254: v1(16.612,36.855) 17.856,36.855 18.999,37.998 27.635,37.998 39.497,49.86 v1(39.497,56.515) ; v1@16.612,36.932 v1@16.789,36.754
SSP0_DETECT: R1.1 X7.11 X11.16@35.4,64 | length 39.6
  Top Layer w0.254: X7.11 16.561,44.55 16.586,44.575 R1.1 ; v1(35.433,61.747) X11.16@35.433,63.967
  Bottom Layer w0.254: v1(16.61,44.55) 29.412,44.55 36.093,51.232 36.093,61.087 v1(35.433,61.747)
SSP2_CS0: X5.10 X11.24@29,64 | length 57.3
  Top Layer w0.203: X11.24@29,64 29,24.492 39.66,13.832 X5.10
SSP2_CS1: X4.10 X11.26 | length 57.5
  Top Layer w0.254: X4.10 17.16,13.35 28.2,24.39 X11.26
SSP2_MISO: X4.7 X5.7 X11.20@30.6,64 | length 94.6
  Top Layer w0.254: X4.7 14.62,5.984 15.164,6.528 19.126,6.528 v1(19.456,6.858) ; X11.20@30.6,64 30.6,25.255 42.266,13.589 42.266,8.509 40.615,6.858 v1@37.368,6.858 ; X5.7 v1@37.12,6.858
  Bottom Layer w0.254: v1(19.456,6.858) v1@37.059,6.858
  other v1: 37.135,6.858
SSP2_MOSI: X4.8 X5.8 X11.22@29.8,64 | length 96.7
  Top Layer w0.254: v1(14.605,14.783) 14.62,14.768 X4.8 ; X11.22@29.8,64 29.8,24.785 41.224,13.36 41.224,8.687 40.411,7.874 37.846,7.874 37.12,8.6 X5.8
  Bottom Layer w0.254: v1(14.605,14.783) 21.184,8.204 v1(37.567,8.204)
SSP2_SCK: X4.9 X5.9 X11.18@31.4,64 | length 100.3
  Top Layer w0.254: X4.9 18.13,3.46 v1(19.583,2.007) ; X11.18@31.4,64 31.4,33.522 37.516,27.407 42.266,27.407 44.806,24.867 44.806,6.731 41.535,3.46 ; X5.9@39.66,5.345 X5.9 41.535,3.46 ; v1(41.377,2.007) 41.377,3.302 41.535,3.46
  Bottom Layer w0.254: v1(19.583,2.007) v1(41.377,2.007)
STATUS: M1.49 R12.2 | length 39.9
  Top Layer w0.254: v1@49.987,26.873 49.987,35.585 58.649,44.247 67.386,44.247 69.5,42.133 M1.49 ; R12.2 v1(50,22.365)
  Bottom Layer w0.254: v1(50,22.365) v1(50,26.873)
UART0_RXD: X6.8 X11.17@31.8,72.2 | length 84.7
  Top Layer w0.254: X11.17@31.8,72.2 31.8,69.013 34.011,66.802 34.011,34.493 38.583,29.921 43.713,29.921 48.514,25.121 57.404,25.121 63.475,19.05 v1(64.033,19.05) ; v1(67.081,14.961) 68.12,13.922 X6.8
  Bottom Layer w0.254: v1(64.033,19.05) 64.033,18.009 v1(67.081,14.961)
UART0_TXD: X6.7 X11.19@31,72.2 | length 94.7
  Top Layer w0.254: X11.19@31,72.2 31,68.746 33.401,66.345 33.401,34.239 38.405,29.235 43.409,29.235 48.108,24.536 56.998,24.536 64.008,17.526 v1(68.148,17.526) ; X6.7 68.148,3.488 v1(68.148,6.629)
  Bottom Layer w0.254: v1(68.148,6.629) v1(68.148,17.526)
UART1_RXD: X11.21@30.2,72.2 X12.10 | length 110.8
  Top Layer w0.254: X11.21@30.2,72.2 30.2,68.631 32.766,66.065 32.766,33.96 38.125,28.6 43.053,28.6 47.727,23.927 56.591,23.927 63.856,16.662 90.424,16.662 93.16,13.926 X12.10
UART1_TXD: X11.23@29.4,72.2 X12.9 | length 115.1
  Top Layer w0.254: X11.23@29.4,72.2 29.4,68.542 32.182,65.761 32.182,33.655 37.846,27.991 42.647,27.991 47.295,23.343 56.261,23.343 63.754,15.85 75.946,15.85 v1(76.835,14.961) ; X12.9 93.167,3.467 v1(93.167,6.655)
  Bottom Layer w0.254: v1(76.835,14.961) 78.664,14.961 86.97,6.655 v1(93.167,6.655)
UART2_RXD: X4.4 X11.28 | length 66.5
  Top Layer w0.254: X4.4 9.54,18.76 14.224,23.444 24.79,23.444 27.4,26.054 X11.28
UART2_TXD: X4.3 X11.30 | length 74.9
  Top Layer w0.254: X4.3 9.54,6.538 8.306,7.772 8.306,18.567 13.868,24.13 24.562,24.13 26.6,26.168 X11.30
UART3_RXD: X6.4 X11.32 | length 86.3
  Top Layer w0.254: v1@25.8,27.203 X11.32 ; X6.4 63.094,11.026 v1(63.094,7.95)
  Bottom Layer w0.254: v1@25.832,27.203 25.832,25.349 39.548,11.633 56.261,11.633 59.944,7.95 v1(63.094,7.95)
  other v1: 25.825,27.203
UART3_TXD: X6.3 X11.34 | length 87.8
  Top Layer w0.254: v1@25,26.314 X11.34 ; X6.3 63.119,3.539 v1(63.119,6.629)
  Bottom Layer w0.254: v1@25.044,26.314 25.044,25.07 39.395,10.719 55.88,10.719 59.969,6.629 v1(63.119,6.629)
  other v1: 25.038,26.314
UART4_RXD: X5.4 X11.36 | length 56.2
  Top Layer w0.254: v1@24.2,27.203 X11.36 ; v1(31.979,14.529) 31.979,11.141 X5.4
  Bottom Layer w0.254: v1@24.206,27.203 24.206,24.867 31.979,17.094 v1(31.979,14.529)
  other v1: 24.199,27.203
UART4_TXD: X5.3 X11.38 | length 66
  Top Layer w0.254: v1@23.4,26.314 X11.38 ; v1(27.432,11.278) 27.432,8.509 28.905,7.036 31.75,7.036 32.08,6.706 32.08,3.5 X5.3
  Bottom Layer w0.254: v1@23.393,26.314 23.393,24.689 27.457,20.625 27.457,11.405 v1@27.635,11.227
  other v1: 23.387,26.314
USB0_D_N: pad.14@59.69,87.693 X9.2 X11.3 | length 40.2
  Top Layer w0.254: X11.3@40.465,72.619 40.465,74.165 40.462,74.168 41.656,75.362 47.295,75.362 52.197,80.264 64.091,80.264 65.405,81.578 65.405,85.681 64.091,86.995 60.388,86.995 X9.2
USB0_D_P: pad.15 X9.3 X11.5 | length 39.2
  Top Layer w0.254: X11.5@39.957,72.796 39.957,73.955 39.954,73.958 39.954,74.378 41.446,75.87 47.084,75.87 51.987,80.772 63.881,80.772 64.897,81.788 64.897,85.471 63.881,86.487 60.484,86.487 pad.15
USB0_ID: pad.24 X10.2 X11.7 | length 17.4
  Top Layer w0.254: X11.7 39,70.753 39.573,70.18 41.808,70.18 42.367,70.739 42.367,73.228 42.85,73.711 48.311,73.711 49.149,74.549 pad.24
USB0_PWR: pad.14@59.69,89.693 pad.22 X9.1 X15.1 | length 17.4
  Top Layer w1.016: X9.1 59.69,91.567 60.706,92.583 64.262,92.583 69,87.845 pad.22
USB1_D_N: M1.12 X11.9 | length 42
  Top Layer w0.254: X11.9 38.2,71.069 38.054,70.923 38.054,69.083 40.488,66.65 43.688,66.65 45.949,68.91 54.305,68.91 60.325,74.93 67.8,74.93 69.215,73.515 69.215,72.319 69.5,72.034 M1.12
USB1_D_P: M1.13 X11.11 | length 42
  Top Layer w0.254: X11.11 37.4,71.069 37.546,70.923 37.546,68.873 40.277,66.142 43.898,66.142 46.159,68.402 54.516,68.402 60.535,74.422 67.589,74.422 68.707,73.304 68.707,72.241 68.5,72.034 M1.13
VDD_4V0: C2.1 C3.1 C4.1 C16.1 C17.1 C18.1 C19.1 L2.2 M1.38 M1.39 M1.62 M1.63 R11.2 | length 124.7
  Top Layer w0.635: 88.138,48.057 53.391,48.057 52.996,47.662 C16.1@52.224,47.662 ; C3.1 88.338,48.5 M1.63 85.95,48.55 53.112,48.55 C16.1@52.224,47.662 ; C18.1 89.138,46.7 C2.1 88.338,47.5 M1.62 85.95,47.55 C16.1@52.112,47.55 ; C16.1@52.112,47.55 C16.1 C16.1@52.224,47.662 ; C16.1@52.112,47.55 C16.1@52.224,47.662
  Top Layer w1.016: R11.2 45.4,47 46.062,47.662 C17.1 ; L2.2@50,45.72 C17.1 ; L2.2@52,45.72 C16.1 C17.1
VRTC: C1.1 M1.42 | length 2.1
  Top Layer w0.381: C1.1 62.3,39.643 62.5,39.843 M1.42
pads on no net: L2.9 L2.10 L2.11 L2.12 L2.13 L2.14 M1.6 M1.7 M1.8 M1.9 M1.15 M1.16 M1.21 M1.22 M1.23 M1.24 M1.25 M1.26 M1.27 M1.28 M1.29 M1.30 M1.31 M1.32 M1.33 M1.34 M1.35 M1.36 M1.45 M1.46 M1.47 M1.48 M1.50 M1.52 M1.53 M1.54 M1.55 M1.56 M1.66 M1.67 M1.68 M1.69 M1.70 M1.71 M1.72 M1.73 M1.74 M1.75 M1.76 M1.83 M1.84 M1.85 M1.86 M1.87 REPER1.1 REPER2.1 REPER3.1 REPER4.1 U1.7 U1.8 U1.9 U1.10 U2.5 U2.9 U2.10 U2.11 U2.12 U2.13 U6.4 U6.7 U6.15 U6.16 U6.17 U6.18 VL1.5 X1.0 X1.7 X2.0 X2.7 X7.13 X7.14 X8.0 X11.14@44.746,70.412 X11.15@43.73,70.412 X11.16@44.746,71.428 X11.17@43.73,71.428 X11.18@44.746,72.444 X11.19@43.73,72.444 X11.20@15.028,70.412 X11.21@14.012,70.412 X11.22@15.028,71.428 X11.23@14.012,71.428 X11.24@15.028,72.444 X11.25@14.012,72.444 X11.R X13.0 X13.1 X13.4 X13.6 X13.7 X13.8 X13.9 X14.0 X14.3 X14.7 X14.8 X14.9 X14.10

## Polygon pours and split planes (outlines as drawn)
GND on Top Layer "Keep-Out Layer-No Net" (solid, remove dead copper, pour order 4): 0,100 100,100 100,0 0,0
GND on Bottom Layer "Keep-Out Layer-No Net" (solid, remove dead copper, pour order 2): 0,100 100,100 100,0 0,0 0,100

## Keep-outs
Keep-Out Layer:
  the board outline again, w0.203

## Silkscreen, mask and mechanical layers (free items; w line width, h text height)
Top Overlay:
  rectangle: 76,26.5 77.5,28
  rectangle: 76,24.5 77.5,26
  rectangle: 76,22.5 77.5,24
  rectangle: 76,20.5 77.5,22
  lines w0.152: 75,28 cw(c76,28) 76,29 86,29 cw(c86,28) 87,28 87,20.5 cw(c86,20.5) 86,19.5 76,19.5 cw(c76,20.5) 75,20.5 75,28 ; 75,28 ccw(c75,28) 75,28
  lines w0.203: 49.784,71.882 48.768,71.882 48.768,74.676 49.784,74.676
  text "5V" at 1.016,87.122 h2.54
  text "USB PWR" at 64.872,86.106 h2.54
  text "USB HOST/DEVICE" at 57.169,76.232 h2.54
  text "ETH1" at 21.615,75.895 h2.54
  text "ETH0" at 38.532,75.743 h2.54
  text "GNSS" at 91.567,59.944 h3.05
  text "3G/4G MODEM" at 63.246,35.814 h3
  text "EV-iMX287-NANO-MB-V2" at 48,31.5 h3.81
  text "www.otladka.com.ua" at 48,29 h2.54
  text "Rev. 1.0" at 61.214,26.67 h2.54
  text "SIM5320" at 78.708,26.63 h2.54
  text "module here." at 26.619,26.594 h3 r90
  text "Place your EV-iMX287-NANO" at 23.978,26.492 h3 r90
  text "SIM5360" at 78.708,24.598 h2.54
  text "SIM6320" at 78.708,22.566 h2.54
  text "RESET" at 5.461,22.225 h2.54
  text "Network LED" at 55.956,21.133 h3
  text "SIM7100" at 78.708,20.534 h2.54
  text "Status LED" at 56.058,17.856 h3
Mechanical 1:
  lines w0.203: -2,-2 102,-2 102,102 -2,102 -2,-2
Mechanical 24:
  circle w0.127: c98.5,93.5 r1.118
  circle w0.127: c1.5,1.5 r1.118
